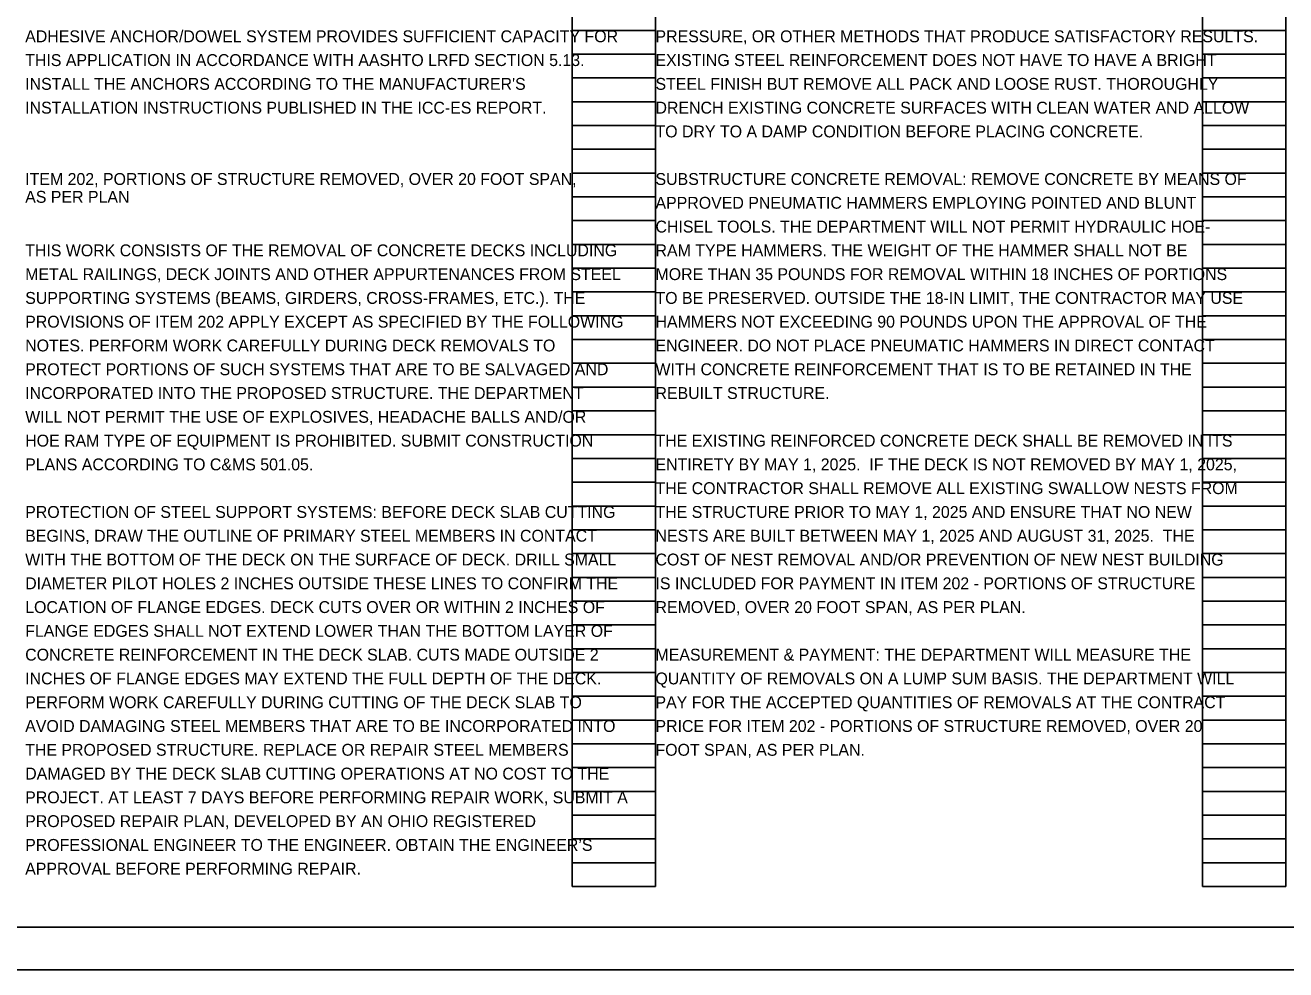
# Model space of a CAD drawing. Extents: x 0 to 49.8, y -1.2 to 22.
# Drawn here: x 9.82 to 24.66, y 0 to 11.12 of the extents above; entities that cross this region are included whole.
import ezdxf

# ---------------------------------------------------------------- set-up
doc = ezdxf.new("R2010")
doc.units = 0
for name, color, linetype in [('SH_Border', 7, 'Continuous'), ('SH_Cut_Line', 7, 'Continuous'), ('SH_Data', 7, 'Continuous'), ('SH_Text', 7, 'Continuous')]:
    doc.layers.add(name, color=color, linetype=linetype)

msp = doc.modelspace()

# ---------------------------------------------------------------- linework, layer by layer
at = {"layer": 'SH_Border'}
msp.add_lwpolyline([(1.5, 21.5), (33.5, 21.5), (33.5, 0.5), (1.5, 0.5)], close=True, dxfattribs=at)
at = {"layer": 'SH_Cut_Line'}
msp.add_lwpolyline([(0, 0), (34, 0), (34, 22), (0, 22)], close=True, dxfattribs=at)
at = {"layer": 'SH_Data'}
for p, q in [((16.26, 0.98), (16.26, 21.14)), ((17.24, 0.98), (17.24, 21.14)), ((23.68, 0.98), (23.68, 21.14)), ((24.66, 0.98), (24.66, 21.14)), ((16.26, 11.06), (17.24, 11.06)), ((23.68, 11.06), (24.66, 11.06)), ((16.26, 10.78), (17.24, 10.78)), ((23.68, 10.78), (24.66, 10.78)), ((16.26, 10.5), (17.24, 10.5)), ((23.68, 10.5), (24.66, 10.5)), ((16.26, 10.22), (17.24, 10.22)), ((23.68, 10.22), (24.66, 10.22)), ((16.26, 9.94), (17.24, 9.94)), ((23.68, 9.94), (24.66, 9.94)), ((16.26, 9.66), (17.24, 9.66)), ((23.68, 9.66), (24.66, 9.66)), ((16.26, 9.38), (17.24, 9.38)), ((23.68, 9.38), (24.66, 9.38)), ((16.26, 9.1), (17.24, 9.1)), ((23.68, 9.1), (24.66, 9.1)), ((16.26, 8.82), (17.24, 8.82)), ((23.68, 8.82), (24.66, 8.82)), ((16.26, 8.54), (17.24, 8.54)), ((23.68, 8.54), (24.66, 8.54)), ((16.26, 8.26), (17.24, 8.26)), ((23.68, 8.26), (24.66, 8.26)), ((16.26, 7.98), (17.24, 7.98)), ((23.68, 7.98), (24.66, 7.98)), ((16.26, 7.7), (17.24, 7.7)), ((23.68, 7.7), (24.66, 7.7)), ((16.26, 7.42), (17.24, 7.42)), ((23.68, 7.42), (24.66, 7.42)), ((16.26, 7.14), (17.24, 7.14)), ((23.68, 7.14), (24.66, 7.14)), ((16.26, 6.86), (17.24, 6.86)), ((23.68, 6.86), (24.66, 6.86)), ((16.26, 6.58), (17.24, 6.58)), ((23.68, 6.58), (24.66, 6.58)), ((16.26, 6.3), (17.24, 6.3)), ((23.68, 6.3), (24.66, 6.3)), ((16.26, 6.02), (17.24, 6.02)), ((23.68, 6.02), (24.66, 6.02)), ((16.26, 5.74), (17.24, 5.74)), ((23.68, 5.74), (24.66, 5.74)), ((16.26, 5.46), (17.24, 5.46)), ((23.68, 5.46), (24.66, 5.46)), ((16.26, 5.18), (17.24, 5.18)), ((23.68, 5.18), (24.66, 5.18)), ((16.26, 4.9), (17.24, 4.9)), ((23.68, 4.9), (24.66, 4.9)), ((16.26, 4.62), (17.24, 4.62)), ((23.68, 4.62), (24.66, 4.62)), ((16.26, 4.34), (17.24, 4.34)), ((23.68, 4.34), (24.66, 4.34)), ((16.26, 4.06), (17.24, 4.06)), ((23.68, 4.06), (24.66, 4.06)), ((16.26, 3.78), (17.24, 3.78)), ((23.68, 3.78), (24.66, 3.78)), ((16.26, 3.5), (17.24, 3.5)), ((23.68, 3.5), (24.66, 3.5)), ((16.26, 3.22), (17.24, 3.22)), ((23.68, 3.22), (24.66, 3.22)), ((16.26, 2.94), (17.24, 2.94)), ((23.68, 2.94), (24.66, 2.94)), ((16.26, 2.66), (17.24, 2.66)), ((23.68, 2.66), (24.66, 2.66)), ((16.26, 2.38), (17.24, 2.38)), ((23.68, 2.38), (24.66, 2.38)), ((16.26, 2.1), (17.24, 2.1)), ((23.68, 2.1), (24.66, 2.1)), ((16.26, 1.82), (17.24, 1.82)), ((23.68, 1.82), (24.66, 1.82)), ((16.26, 1.54), (17.24, 1.54)), ((23.68, 1.54), (24.66, 1.54)), ((16.26, 1.26), (17.24, 1.26)), ((23.68, 1.26), (24.66, 1.26)), ((16.26, 0.98), (17.24, 0.98)), ((23.68, 0.98), (24.66, 0.98))]:
    msp.add_line(p, q, dxfattribs=at)

# ---------------------------------------------------------------- texts
at = {"layer": 'SH_Text'}
for s, p in [('ADHESIVE ANCHOR/DOWEL SYSTEM PROVIDES SUFFICIENT CAPACITY FOR ', (9.82, 10.92)), ('PRESSURE, OR OTHER METHODS THAT PRODUCE SATISFACTORY RESULTS. ', (17.24, 10.92)), ('THIS APPLICATION IN ACCORDANCE WITH AASHTO LRFD SECTION 5.13. ', (9.82, 10.64)), ('EXISTING STEEL REINFORCEMENT DOES NOT HAVE TO HAVE A BRIGHT ', (17.24, 10.64)), ("INSTALL THE ANCHORS ACCORDING TO THE MANUFACTURER'S ", (9.82, 10.36)), ('STEEL FINISH BUT REMOVE ALL PACK AND LOOSE RUST. THOROUGHLY ', (17.24, 10.36)), ('INSTALLATION INSTRUCTIONS PUBLISHED IN THE ICC-ES REPORT.', (9.82, 10.08)), ('DRENCH EXISTING CONCRETE SURFACES WITH CLEAN WATER AND ALLOW ', (17.24, 10.08)), ('TO DRY TO A DAMP CONDITION BEFORE PLACING CONCRETE.', (17.24, 9.8)), ('ITEM 202, PORTIONS OF STRUCTURE REMOVED, OVER 20 FOOT SPAN, ', (9.82, 9.24)), ('SUBSTRUCTURE CONCRETE REMOVAL: REMOVE CONCRETE BY MEANS OF ', (17.24, 9.24)), ('AS PER PLAN', (9.82, 9.03)), ('APPROVED PNEUMATIC HAMMERS EMPLOYING POINTED AND BLUNT ', (17.24, 8.96)), ('CHISEL TOOLS. THE DEPARTMENT WILL NOT PERMIT HYDRAULIC HOE-', (17.24, 8.68)), ('THIS WORK CONSISTS OF THE REMOVAL OF CONCRETE DECKS INCLUDING ', (9.82, 8.4)), ('RAM TYPE HAMMERS. THE WEIGHT OF THE HAMMER SHALL NOT BE ', (17.24, 8.4)), ('METAL RAILINGS, DECK JOINTS AND OTHER APPURTENANCES FROM STEEL ', (9.82, 8.12)), ('MORE THAN 35 POUNDS FOR REMOVAL WITHIN 18 INCHES OF PORTIONS ', (17.24, 8.12)), ('SUPPORTING SYSTEMS (BEAMS, GIRDERS, CROSS-FRAMES, ETC.). THE ', (9.82, 7.84)), ('TO BE PRESERVED. OUTSIDE THE 18-IN LIMIT, THE CONTRACTOR MAY USE ', (17.24, 7.84)), ('PROVISIONS OF ITEM 202 APPLY EXCEPT AS SPECIFIED BY THE FOLLOWING ', (9.82, 7.56)), ('HAMMERS NOT EXCEEDING 90 POUNDS UPON THE APPROVAL OF THE ', (17.24, 7.56)), ('NOTES. PERFORM WORK CAREFULLY DURING DECK REMOVALS TO ', (9.82, 7.28)), ('ENGINEER. DO NOT PLACE PNEUMATIC HAMMERS IN DIRECT CONTACT ', (17.24, 7.28)), ('PROTECT PORTIONS OF SUCH SYSTEMS THAT ARE TO BE SALVAGED AND ', (9.82, 7)), ('WITH CONCRETE REINFORCEMENT THAT IS TO BE RETAINED IN THE ', (17.24, 7)), ('INCORPORATED INTO THE PROPOSED STRUCTURE. THE DEPARTMENT ', (9.82, 6.72)), ('REBUILT STRUCTURE.', (17.24, 6.72)), ('WILL NOT PERMIT THE USE OF EXPLOSIVES, HEADACHE BALLS AND/OR ', (9.82, 6.44)), ('HOE RAM TYPE OF EQUIPMENT IS PROHIBITED. SUBMIT CONSTRUCTION ', (9.82, 6.16)), ('THE EXISTING REINFORCED CONCRETE DECK SHALL BE REMOVED IN ITS ', (17.24, 6.16)), ('PLANS ACCORDING TO C&MS 501.05.', (9.82, 5.88)), ('ENTIRETY BY MAY 1, 2025.\xa0 IF THE DECK IS NOT REMOVED BY MAY 1, 2025, ', (17.24, 5.88)), ('THE CONTRACTOR SHALL REMOVE ALL EXISTING SWALLOW NESTS FROM ', (17.24, 5.6)), ('PROTECTION OF STEEL SUPPORT SYSTEMS: BEFORE DECK SLAB CUTTING ', (9.82, 5.32)), ('THE STRUCTURE PRIOR TO MAY 1, 2025 AND ENSURE THAT NO NEW ', (17.24, 5.32)), ('BEGINS, DRAW THE OUTLINE OF PRIMARY STEEL MEMBERS IN CONTACT ', (9.82, 5.04)), ('NESTS ARE BUILT BETWEEN MAY 1, 2025 AND AUGUST 31, 2025.\xa0 THE ', (17.24, 5.04)), ('WITH THE BOTTOM OF THE DECK ON THE SURFACE OF DECK. DRILL SMALL ', (9.82, 4.76)), ('COST OF NEST REMOVAL AND/OR PREVENTION OF NEW NEST BUILDING ', (17.24, 4.76)), ('DIAMETER PILOT HOLES 2 INCHES OUTSIDE THESE LINES TO CONFIRM THE ', (9.82, 4.48)), ('IS INCLUDED FOR PAYMENT IN ITEM 202 - PORTIONS OF STRUCTURE ', (17.24, 4.48)), ('LOCATION OF FLANGE EDGES. DECK CUTS OVER OR WITHIN 2 INCHES OF ', (9.82, 4.2)), ('REMOVED, OVER 20 FOOT SPAN, AS PER PLAN.', (17.24, 4.2)), ('FLANGE EDGES SHALL NOT EXTEND LOWER THAN THE BOTTOM LAYER OF ', (9.82, 3.92)), ('CONCRETE REINFORCEMENT IN THE DECK SLAB. CUTS MADE OUTSIDE 2 ', (9.82, 3.64)), ('MEASUREMENT & PAYMENT: THE DEPARTMENT WILL MEASURE THE ', (17.24, 3.64)), ('INCHES OF FLANGE EDGES MAY EXTEND THE FULL DEPTH OF THE DECK. ', (9.82, 3.36)), ('QUANTITY OF REMOVALS ON A LUMP SUM BASIS. THE DEPARTMENT WILL ', (17.24, 3.36)), ('PERFORM WORK CAREFULLY DURING CUTTING OF THE DECK SLAB TO ', (9.82, 3.08)), ('PAY FOR THE ACCEPTED QUANTITIES OF REMOVALS AT THE CONTRACT ', (17.24, 3.08)), ('AVOID DAMAGING STEEL MEMBERS THAT ARE TO BE INCORPORATED INTO ', (9.82, 2.8)), ('PRICE FOR ITEM 202 - PORTIONS OF STRUCTURE REMOVED, OVER 20 ', (17.24, 2.8)), ('THE PROPOSED STRUCTURE. REPLACE OR REPAIR STEEL MEMBERS ', (9.82, 2.52)), ('FOOT SPAN, AS PER PLAN.', (17.24, 2.52)), ('DAMAGED BY THE DECK SLAB CUTTING OPERATIONS AT NO COST TO THE ', (9.82, 2.24)), ('PROJECT. AT LEAST 7 DAYS BEFORE PERFORMING REPAIR WORK, SUBMIT A ', (9.82, 1.96)), ('PROPOSED REPAIR PLAN, DEVELOPED BY AN OHIO REGISTERED ', (9.82, 1.68)), ('PROFESSIONAL ENGINEER TO THE ENGINEER. OBTAIN THE ENGINEER’S ', (9.82, 1.4)), ('APPROVAL BEFORE PERFORMING REPAIR.', (9.82, 1.12))]:
    msp.add_text(s, height=0.14, dxfattribs=at).set_placement(p)

doc.saveas('drawing.dxf')
